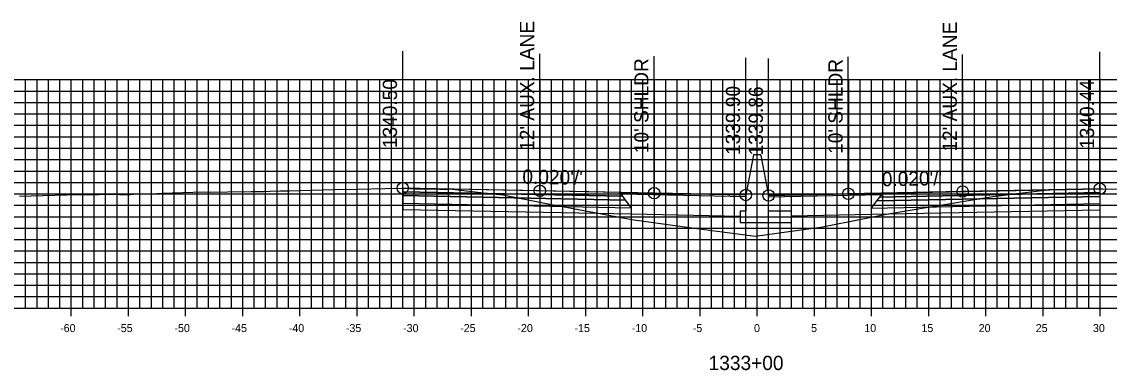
# Model space of a CAD drawing. Extents: x 674939 to 678919, y 750652 to 765176.
# Drawn here: x 678674.2 to 678769.3, y 752192.1 to 752222.6 of the extents above; entities that cross this region are included whole.
import ezdxf

# ---------------------------------------------------------------- set-up
doc = ezdxf.new("R2010")
doc.units = 0
for name, color, linetype in [('R_Alt Surface', 7, 'Continuous'), ('R_Axis', 7, 'Continuous'), ('R_Axis Annot', 7, 'Continuous'), ('R_Exist Surface', 7, 'Continuous'), ('R_Fin Surface', 7, 'Continuous'), ('R_Grid', 7, 'Continuous'), ('R_No Plot', 7, 'Continuous'), ('R_Proposed Road', 7, 'Continuous'), ('R_Xsect Elev', 7, 'Continuous'), ('R_Xsect Slope', 7, 'Continuous')]:
    doc.layers.add(name, color=color, linetype=linetype)

msp = doc.modelspace()

# ---------------------------------------------------------------- linework, layer by layer
at = {"layer": 'R_Alt Surface'}
for points in [[(678707.522, 752207.724), (678707.522, 752207.394), (678727.022, 752207.004), (678726.772, 752207.339)], [(678707.522, 752207.394), (678707.522, 752206.734), (678727.522, 752206.334), (678727.022, 752207.004)], [(678768.503, 752207.33), (678768.503, 752206.67), (678748.503, 752206.27), (678749.003, 752206.94)], [(678768.503, 752207.66), (678768.503, 752207.33), (678749.003, 752206.94), (678749.253, 752207.275)]]:
    msp.add_lwpolyline(points, close=True, dxfattribs=at)
for points in [[(678707.522, 752206.734), (678707.522, 752206.194), (678727.522, 752205.794), (678737.033, 752205.604)], [(678768.503, 752206.67), (678768.503, 752206.13), (678748.503, 752205.73), (678741.533, 752205.591)]]:
    msp.add_lwpolyline(points, dxfattribs=at)
at = {"layer": 'R_Axis'}
for p, q in [((678678.533, 752196.851), (678678.533, 752198.251)), ((678683.533, 752196.851), (678683.533, 752198.251)), ((678688.533, 752196.851), (678688.533, 752198.251)), ((678693.533, 752196.851), (678693.533, 752198.251)), ((678698.533, 752196.851), (678698.533, 752198.251)), ((678703.533, 752196.851), (678703.533, 752198.251)), ((678708.533, 752196.851), (678708.533, 752198.251)), ((678713.533, 752196.851), (678713.533, 752198.251)), ((678718.533, 752196.851), (678718.533, 752198.251)), ((678723.533, 752196.851), (678723.533, 752198.251)), ((678728.533, 752196.851), (678728.533, 752198.251)), ((678733.533, 752196.851), (678733.533, 752198.251)), ((678738.533, 752196.851), (678738.533, 752198.251)), ((678743.533, 752196.851), (678743.533, 752198.251)), ((678748.533, 752196.851), (678748.533, 752198.251)), ((678753.533, 752196.851), (678753.533, 752198.251)), ((678758.533, 752196.851), (678758.533, 752198.251)), ((678763.533, 752196.851), (678763.533, 752198.251)), ((678768.533, 752196.851), (678768.533, 752198.251)), ((678638.533, 752197.551), (678838.533, 752197.551))]:
    msp.add_line(p, q, dxfattribs=at)
at = {"layer": 'R_Exist Surface'}
msp.add_lwpolyline([(678673.991, 752207.357), (678676.045, 752207.407), (678678.149, 752207.456), (678679.755, 752207.484), (678680.975, 752207.507), (678681.866, 752207.519), (678682.753, 752207.501), (678683.288, 752207.49), (678683.509, 752207.485), (678683.696, 752207.504), (678683.917, 752207.52), (678683.998, 752207.529), (678684.331, 752207.552), (678684.664, 752207.546), (678685.466, 752207.56), (678686.02, 752207.58), (678686.464, 752207.6), (678688.246, 752207.657), (678690.131, 752207.715), (678690.686, 752207.707), (678692.2, 752207.718), (678694.308, 752207.753), (678695.198, 752207.768), (678695.376, 752207.766), (678695.931, 752207.778), (678696.821, 752207.813), (678697.621, 752207.829), (678701.51, 752207.927), (678703.554, 752207.973), (678706, 752208.029), (678707.515, 752208.055), (678707.522, 752208.054), (678707.605, 752208.056), (678708.155, 752208.011), (678708.51, 752207.987), (678708.844, 752207.976), (678709.066, 752207.993), (678710.219, 752207.977), (678711.221, 752207.942), (678711.435, 752207.957), (678711.603, 752207.984), (678714.839, 752207.604), (678716.282, 752207.458), (678720.099, 752206.694), (678727.575, 752205.309), (678732.805, 752204.59), (678738.35, 752203.836), (678742.141, 752204.365), (678744.09, 752204.636), (678747.917, 752205.405), (678749.675, 752205.753), (678752.092, 752206.165), (678759.153, 752207.324), (678763.208, 752207.812), (678764.271, 752207.942), (678764.286, 752207.937), (678764.491, 752207.936), (678766.574, 752207.965), (678766.745, 752207.973), (678766.779, 752207.967), (678766.983, 752207.969), (678768.145, 752207.979), (678768.233, 752207.983), (678768.503, 752207.99), (678768.552, 752207.992), (678768.779, 752207.998), (678772.593, 752207.91)], dxfattribs=at)
at = {"layer": 'R_Fin Surface'}
for points in [[(678737.533, 752207.454), (678729.522, 752207.614), (678719.522, 752207.814), (678707.522, 752208.054)], [(678768.503, 752207.99), (678756.503, 752207.75), (678746.503, 752207.55), (678739.533, 752207.411)]]:
    msp.add_lwpolyline(points, dxfattribs=at)
for points in [[(678707.522, 752208.054), (678707.522, 752207.724), (678726.772, 752207.339), (678726.522, 752207.674)], [(678726.522, 752207.674), (678737.533, 752207.454), (678737.537, 752207.297), (678726.642, 752207.514)], [(678749.384, 752207.451), (678739.533, 752207.254), (678739.533, 752207.411), (678749.503, 752207.61)], [(678768.503, 752207.99), (678768.503, 752207.66), (678749.253, 752207.275), (678749.503, 752207.61)]]:
    msp.add_lwpolyline(points, close=True, dxfattribs=at)
at = {"layer": 'R_Grid'}
for p, q in [((678638.533, 752217.551), (678838.533, 752217.551)), ((678674.533, 752197.551), (678674.533, 752217.551)), ((678675.533, 752197.551), (678675.533, 752217.551)), ((678676.533, 752197.551), (678676.533, 752217.551)), ((678677.533, 752197.551), (678677.533, 752217.551)), ((678678.533, 752197.551), (678678.533, 752217.551)), ((678679.533, 752197.551), (678679.533, 752217.551)), ((678680.533, 752197.551), (678680.533, 752217.551)), ((678681.533, 752197.551), (678681.533, 752217.551)), ((678682.533, 752197.551), (678682.533, 752217.551)), ((678683.533, 752197.551), (678683.533, 752217.551)), ((678684.533, 752197.551), (678684.533, 752217.551)), ((678685.533, 752197.551), (678685.533, 752217.551)), ((678686.533, 752197.551), (678686.533, 752217.551)), ((678687.533, 752197.551), (678687.533, 752217.551)), ((678688.533, 752197.551), (678688.533, 752217.551)), ((678689.533, 752197.551), (678689.533, 752217.551)), ((678690.533, 752197.551), (678690.533, 752217.551)), ((678691.533, 752197.551), (678691.533, 752217.551)), ((678692.533, 752197.551), (678692.533, 752217.551)), ((678693.533, 752197.551), (678693.533, 752217.551)), ((678694.533, 752197.551), (678694.533, 752217.551)), ((678695.533, 752197.551), (678695.533, 752217.551)), ((678696.533, 752197.551), (678696.533, 752217.551)), ((678697.533, 752197.551), (678697.533, 752217.551)), ((678698.533, 752197.551), (678698.533, 752217.551)), ((678699.533, 752197.551), (678699.533, 752217.551)), ((678700.533, 752197.551), (678700.533, 752217.551)), ((678701.533, 752197.551), (678701.533, 752217.551)), ((678702.533, 752197.551), (678702.533, 752217.551)), ((678703.533, 752197.551), (678703.533, 752217.551)), ((678704.533, 752197.551), (678704.533, 752217.551)), ((678705.533, 752197.551), (678705.533, 752217.551)), ((678706.533, 752197.551), (678706.533, 752217.551)), ((678707.533, 752197.551), (678707.533, 752217.551)), ((678708.533, 752197.551), (678708.533, 752217.551)), ((678709.533, 752197.551), (678709.533, 752217.551)), ((678710.533, 752197.551), (678710.533, 752217.551)), ((678711.533, 752197.551), (678711.533, 752217.551)), ((678712.533, 752197.551), (678712.533, 752217.551)), ((678713.533, 752197.551), (678713.533, 752217.551)), ((678714.533, 752197.551), (678714.533, 752217.551)), ((678715.533, 752197.551), (678715.533, 752217.551)), ((678716.533, 752197.551), (678716.533, 752217.551)), ((678717.533, 752197.551), (678717.533, 752217.551)), ((678718.533, 752197.551), (678718.533, 752217.551)), ((678719.533, 752197.551), (678719.533, 752217.551)), ((678720.533, 752197.551), (678720.533, 752217.551)), ((678721.533, 752197.551), (678721.533, 752217.551)), ((678722.533, 752197.551), (678722.533, 752217.551)), ((678723.533, 752197.551), (678723.533, 752217.551)), ((678724.533, 752197.551), (678724.533, 752217.551)), ((678725.533, 752197.551), (678725.533, 752217.551)), ((678726.533, 752197.551), (678726.533, 752217.551)), ((678727.533, 752197.551), (678727.533, 752217.551)), ((678728.533, 752197.551), (678728.533, 752217.551)), ((678729.533, 752197.551), (678729.533, 752217.551)), ((678730.533, 752197.551), (678730.533, 752217.551)), ((678731.533, 752197.551), (678731.533, 752217.551)), ((678732.533, 752197.551), (678732.533, 752217.551)), ((678733.533, 752197.551), (678733.533, 752217.551)), ((678734.533, 752197.551), (678734.533, 752217.551)), ((678735.533, 752197.551), (678735.533, 752217.551)), ((678736.533, 752197.551), (678736.533, 752217.551)), ((678737.533, 752197.551), (678737.533, 752217.551)), ((678738.533, 752197.551), (678738.533, 752217.551)), ((678739.533, 752197.551), (678739.533, 752217.551)), ((678740.533, 752197.551), (678740.533, 752217.551)), ((678741.533, 752197.551), (678741.533, 752217.551)), ((678742.533, 752197.551), (678742.533, 752217.551)), ((678743.533, 752197.551), (678743.533, 752217.551)), ((678744.533, 752197.551), (678744.533, 752217.551)), ((678745.533, 752197.551), (678745.533, 752217.551)), ((678746.533, 752197.551), (678746.533, 752217.551)), ((678747.533, 752197.551), (678747.533, 752217.551)), ((678748.533, 752197.551), (678748.533, 752217.551)), ((678749.533, 752197.551), (678749.533, 752217.551)), ((678750.533, 752197.551), (678750.533, 752217.551)), ((678751.533, 752197.551), (678751.533, 752217.551)), ((678752.533, 752197.551), (678752.533, 752217.551)), ((678753.533, 752197.551), (678753.533, 752217.551)), ((678754.533, 752197.551), (678754.533, 752217.551)), ((678755.533, 752197.551), (678755.533, 752217.551)), ((678756.533, 752197.551), (678756.533, 752217.551)), ((678757.533, 752197.551), (678757.533, 752217.551)), ((678758.533, 752197.551), (678758.533, 752217.551)), ((678759.533, 752197.551), (678759.533, 752217.551)), ((678760.533, 752197.551), (678760.533, 752217.551)), ((678761.533, 752197.551), (678761.533, 752217.551)), ((678762.533, 752197.551), (678762.533, 752217.551)), ((678763.533, 752197.551), (678763.533, 752217.551)), ((678764.533, 752197.551), (678764.533, 752217.551)), ((678765.533, 752197.551), (678765.533, 752217.551)), ((678766.533, 752197.551), (678766.533, 752217.551)), ((678767.533, 752197.551), (678767.533, 752217.551)), ((678768.533, 752197.551), (678768.533, 752217.551)), ((678638.533, 752216.551), (678838.533, 752216.551)), ((678638.533, 752215.551), (678838.533, 752215.551)), ((678638.533, 752214.551), (678838.533, 752214.551)), ((678638.533, 752213.551), (678838.533, 752213.551)), ((678638.533, 752212.551), (678838.533, 752212.551)), ((678638.533, 752211.551), (678838.533, 752211.551)), ((678638.533, 752210.551), (678838.533, 752210.551)), ((678638.533, 752209.551), (678838.533, 752209.551)), ((678638.533, 752208.551), (678838.533, 752208.551)), ((678638.533, 752207.551), (678838.533, 752207.551)), ((678638.533, 752206.551), (678838.533, 752206.551)), ((678638.533, 752205.551), (678838.533, 752205.551)), ((678638.533, 752204.551), (678838.533, 752204.551)), ((678638.533, 752203.551), (678838.533, 752203.551)), ((678638.533, 752202.551), (678838.533, 752202.551)), ((678638.533, 752201.551), (678838.533, 752201.551)), ((678638.533, 752200.551), (678838.533, 752200.551)), ((678638.533, 752199.551), (678838.533, 752199.551)), ((678638.533, 752198.551), (678838.533, 752198.551)), ((678638.533, 752197.551), (678838.533, 752197.551))]:
    msp.add_line(p, q, dxfattribs=at)
at = {"layer": 'R_No Plot'}
for centre in [(678707.522, 752208.054), (678719.522, 752207.814), (678756.503, 752207.75), (678768.503, 752207.99), (678729.522, 752207.614), (678737.533, 752207.454), (678739.533, 752207.411), (678746.503, 752207.55)]:
    msp.add_circle(centre, 0.5, dxfattribs=at)
at = {"layer": 'R_Proposed Road'}
for points in [[(678738.203, 752210.954), (678737.533, 752207.454)], [(678738.863, 752210.911), (678738.863, 752210.954), (678738.203, 752210.954), (678738.203, 752210.954)], [(678738.863, 752210.911), (678739.533, 752207.411)], [(678737.533, 752207.454), (678737.533, 752206.036), (678737.033, 752206.036), (678737.033, 752205.036), (678741.533, 752205.036), (678741.533, 752206.036), (678739.533, 752206.036), (678739.533, 752207.411)]]:
    msp.add_lwpolyline(points, dxfattribs=at)
at = {"layer": 'R_Xsect Elev'}
for p, q in [((678707.522, 752208.054), (678707.522, 752220.054)), ((678719.522, 752207.814), (678719.522, 752219.814)), ((678729.522, 752207.614), (678729.522, 752219.614)), ((678756.503, 752207.75), (678756.503, 752219.75)), ((678768.503, 752207.99), (678768.503, 752219.99)), ((678737.533, 752207.454), (678737.533, 752219.454)), ((678739.533, 752207.411), (678739.533, 752219.411)), ((678746.503, 752207.55), (678746.503, 752219.55))]:
    msp.add_line(p, q, dxfattribs=at)

# ---------------------------------------------------------------- texts
at = {"layer": 'R_Axis Annot'}
for s, height, p in [('-60', 0.7, (678677.552, 752195.451)), ('-55', 0.7, (678682.546, 752195.451)), ('-50', 0.7, (678687.552, 752195.451)), ('-45', 0.7, (678692.546, 752195.451)), ('-40', 0.7, (678697.552, 752195.451)), ('-35', 0.7, (678702.546, 752195.451)), ('-30', 0.7, (678707.552, 752195.451)), ('-25', 0.7, (678712.546, 752195.451)), ('-20', 0.7, (678717.552, 752195.451)), ('-15', 0.7, (678722.546, 752195.451)), ('-10', 0.7, (678727.552, 752195.451)), ('-5', 0.7, (678732.896, 752195.451)), ('0', 0.7, (678738.252, 752195.451)), ('5', 0.7, (678743.246, 752195.451)), ('10', 0.7, (678747.902, 752195.451)), ('15', 0.7, (678752.896, 752195.451)), ('20', 0.7, (678757.902, 752195.451)), ('25', 0.7, (678762.896, 752195.451)), ('30', 0.7, (678767.902, 752195.451)), ('1333+00', 1.25, (678734.281, 752192.126))]:
    msp.add_text(s, height=height, dxfattribs=at).set_placement(p)
at = {"layer": 'R_Xsect Elev'}
for s, p in [("12' AUX. LANE", (678719.022, 752211.314)), ("12' AUX. LANE", (678756.003, 752211.25)), ("10' SHLDR", (678729.022, 752211.114)), ("10' SHLDR", (678746.003, 752211.05)), ('1340.50', (678707.022, 752211.554)), ('1339.90', (678737.033, 752210.954)), ('1339.86', (678739.033, 752210.911)), ('1340.44', (678768.003, 752211.49))]:
    msp.add_text(s, height=1.25, rotation=90, dxfattribs=at).set_placement(p)
at = {"layer": 'R_Xsect Slope'}
for rotation, p in [(358.85424, (678717.978, 752208.445)), (1.14576, (678749.444, 752208.209))]:
    msp.add_text("0.020'/'", height=1.25, rotation=rotation, dxfattribs=at).set_placement(p)

doc.saveas('drawing.dxf')
